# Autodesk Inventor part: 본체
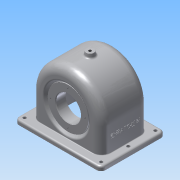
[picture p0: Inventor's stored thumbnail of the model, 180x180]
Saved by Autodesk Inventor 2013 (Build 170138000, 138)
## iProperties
Created: 2015-09
Part Number: 본체
Material: 알루미늄 6061
Document SubType Name: Modeling
Designer: Administrator
Density: 2.71 g/cm^3
Mass: 723.373 g
Surface Area: 889.376 cm^2
Volume: 266.927 cm^3
Author: Administrator
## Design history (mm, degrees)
sketch "스케치1"
  geometry: L1 (-57, -47)-(57, -47); L2 (57, -47)-(57, 0); L3 (-57, -47)-(-57, 0); A1 r 57 centre (0, 0) between (57, 0) and (-57, 0); 1 further point
  constraints: 6 end point, 2 coincident, 2 point on circle, 2 tangent, 1 centre point, 1 horizontal, 1 parallel, 1 perpendicular
  dimensions: "d0" = 47 distance from line of point (0, 0) L1; "d1" = 114 distance of L1.start L1.end
extrude "돌출1" new body sketch "스케치1" stored distance "d2" = 77; taper "d3" = 0 deg
sketch "스케치2"
  geometry: L1 (-6, 13.5)-(120, 13.5); L2 (127, 6.5)-(127, -83.5); L3 (120, -90.5)-(-6, -90.5); L4 (-13, -83.5)-(-13, 6.5); A1 r 7 centre (-6, 6.5) between (-6, 13.5) and (-13, 6.5); A2 r 7 centre (-6, -83.5) between (-13, -83.5) and (-6, -90.5); A3 r 7 centre (120, -83.5) between (120, -90.5) and (127, -83.5); A4 r 7 centre (120, 6.5) between (127, 6.5) and (120, 13.5); 6 further points
  constraints: 8 end point, 8 point on circle, 8 tangent, 6 point on line, 4 centre point, 3 equal radius, 2 midpoint, 2 parallel, 1 horizontal, 1 horizontal alignment, 1 perpendicular, 1 vertical alignment
  dimensions: "d4" = 104 distance of point (127, 13.5) point (127, -90.5); "d6" = 140 distance of point (127, -90.5) point (-13, -90.5); "d7" = 7 radius of A1
extrude "돌출2" join sketch "스케치2" distance "d8" = 7; taper "d9" = 0 deg
sketch "스케치3"
  geometry: C1 r 31 at (0, 0); 1 further point
  constraints: 1 centre point, 1 coincident
  dimensions: "d10" = 62 diameter of C1
extrude "돌출3" join sketch "스케치3" distance "d12" = 10; taper "d13" = 0 deg
sketch "스케치4"
  geometry: L1 (63, -47)-(-63, -47) reference; L2 (-51, 0)-(-51, -47); L3 (51, 0)-(51, -47); A1 r 57 centre (0, 0) between (57, 0) and (-57, 0) reference; A2 r 51 centre (0, 0) between (51, 0) and (-51, 0); 1 further point
  constraints: 4 end point, 2 point on circle, 2 point on line, 2 tangent, 1 centre point, 1 parallel, 1 perpendicular
  dimensions: "d14" = 6 radial gap between concentric circles of A1 A2
extrude "돌출4" cut sketch "스케치4" stored distance "d15" = 67; taper "d16" = 0 deg
sketch "스케치5"
  geometry: L1 (51, 33.5)-(0, 33.5) reference; L2 (0, 0)-(0, 33.5); L3 (0, 19.5)-(28, 19.5); L4 (28, 19.5)-(39.747, 33.5); L5 (57, 38.5)-(0, 38.5) reference
  constraints: 6 end point, 2 point on line, 1 perpendicular
  dimensions: "d17" = 56 diameter of L3.end L2; "d19" = 50 deg angle of L4 L3; "d21" = 19 distance between parallel lines of L3 L5
revolve "회전1" sketch "스케치5" stored, may be unused: angle "d22" = 90 deg
sketch "스케치6"
  geometry: L1 (0, 38.5)-(-40, 38.5) reference; L2 (57, 38.5)-(0, 38.5) reference; L3 (0, 0)-(0, 38.5); L4 (0, 35.5)-(33, 35.5); L5 (39.747, 33.5)-(28, 19.5) reference; L6 (37.416, 38.5)-(33.883, 34.29); L7 (33, 35.5)-(33, 34.611); A1 r 0.5 centre (33.5, 34.611) between (33, 34.611) and (33.883, 34.29); 1 further point
  constraints: 8 end point, 2 perpendicular, 2 point on circle, 2 point on line, 2 tangent, 1 centre point, 1 parallel
  dimensions: "d23" = 3 distance between parallel lines of L4 L2; "d25" = 5 distance between parallel lines of L5 L6; "d26" = 66 diameter of L7 L3; "d27" = 0.5 radius of A1
revolve "회전2" sketch "스케치6" stored, may be unused: angle "d28" = 90 deg
node "작업 평면2"
  node "작업 평면1"
sketch "스케치11"
  geometry: C1 r 6 at (0, 0); 1 further point
  constraints: 1 centre point, 1 coincident
  dimensions: "d81" = 12 diameter of C1
extrude "돌출5" join sketch "스케치11" distance "d83" = 10; taper "d84" = 10 deg
sketch "스케치7"
  geometry: A1 r 28 centre (0, 0) between (0, 28) and (0, -28); 3 further points
  constraints: 4 point on circle, 2 horizontal alignment, 2 vertical alignment, 1 centre point, 1 coincident
  dimensions: "d29" = 56 diameter of A1
hole "구멍1" sketch "스케치7" at (0, 28), (0, -28), (-28, 0), (28, 0) diameter "d31" = 2.459; stored, may be unused: countersink angle "d35" = 90 deg, drill point angle "d37" = 118 deg; dims "d32" = 7, "d33" = 4, "d34" = 2, "d36" = 9
sketch "스케치8"
  geometry: A1 r 24 centre (0, 0) between (0, 24) and (0, -24); 3 further points
  constraints: 4 point on circle, 2 horizontal alignment, 2 vertical alignment, 1 centre point, 1 coincident
  dimensions: "d38" = 48 diameter of A1
hole "구멍2" sketch "스케치8" at (0, 24), (0, -24), (-24, 0), (24, 0) diameter "d40" = 2.459; stored, may be unused: countersink angle "d44" = 90 deg, drill point angle "d46" = 118 deg; dims "d41" = 6, "d42" = 4, "d43" = 2, "d45" = 8
hole "구멍3" diameter "d49" = 40; stored, may be unused: countersink angle "d53" = 90 deg, drill point angle "d55" = 0 deg; dims "d47" = 10, "d48" = 10, "d50" = 6, "d51" = 4, "d52" = 2, "d54" = 16
hole "구멍4" diameter "d58" = 40; stored, may be unused: countersink angle "d62" = 90 deg, drill point angle "d64" = 0 deg; dims "d56" = 10, "d57" = 10, "d59" = 6, "d60" = 4, "d61" = 2, "d63" = 15
sketch "스케치9"
  geometry: 7 further points
  constraints: 4 horizontal alignment, 4 vertical alignment
  dimensions: "d65" = 124 distance of point (119, -38.5) point (-5, -38.5); "d67" = 62 distance of point (57, -38.5) point (-5, -38.5); "d68" = 44 distance of point (-5, -38.5) point (-5, -82.5); "d69" = 44 distance of point (-5, 5.5) point (-5, -38.5)
hole "구멍5" sketch "스케치9" at (-5, -38.5), (119, -38.5), (-5, -82.5), (-5, 5.5), (119, -82.5), (119, 5.5) diameter "d70" = 5; stored, may be unused: countersink angle "d74" = 90 deg, drill point angle "d76" = 0 deg; dims "d71" = 6, "d72" = 4, "d73" = 2, "d75" = 15
hole "구멍6" diameter "d87" = 4.459; stored, may be unused: countersink angle "d91" = 90 deg, drill point angle "d93" = 0 deg; dims "d85" = 10, "d86" = 10, "d88" = 12, "d89" = 4, "d90" = 2, "d92" = 15
sketch "스케치10"
  geometry: L1 (13.613, -31.061)-(63.387, -31.061); L2 (63.387, -31.061)-(63.387, -2.939); L3 (63.387, -2.939)-(13.613, -2.939); L4 (13.613, -2.939)-(13.613, -31.061); L5 (77, 0)-(0, 0) reference; L6 (-6.5, -40)-(83.5, -40) reference; L7 (0, -40)-(0, 0) reference; L8 (-6.5, -47)-(83.5, -47) reference; 7 further points
  constraints: 5 midpoint, 2 vertical alignment, 1 horizontal alignment, 2 other
  dimensions: "d105" = 30 distance from line of point (13.613, -17) L8
feature "엠보싱1" sketch "스케치10" dims "d0" = 47, "d1" = 114, "d78" = 0.5, "d79" = 0
chamfer "모따기1" distance "d94" = 1; stored, may be unused: second distance "d95" = 2, angle "d96" = 45 deg
fillet "모깎기1" dims "d97" = 14
fillet "모깎기2" dims "d98" = 9
fillet "모깎기4" dims "d100" = 3
fillet "모깎기5" dims "d101" = 3
fillet "모깎기7" dims "d103" = 3
fillet "모깎기8" dims "d104" = 1
node "솔리드1"
other parameters: "d80" = 6
